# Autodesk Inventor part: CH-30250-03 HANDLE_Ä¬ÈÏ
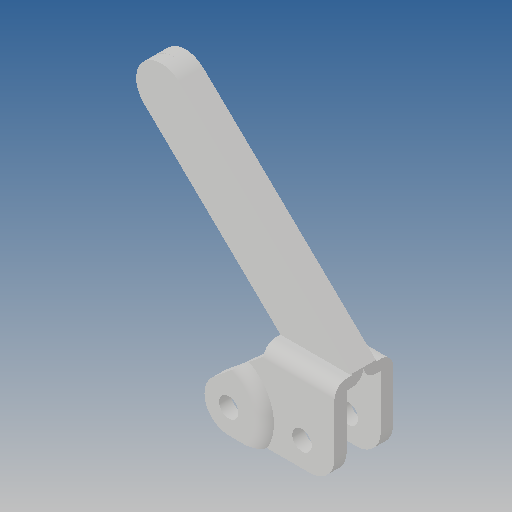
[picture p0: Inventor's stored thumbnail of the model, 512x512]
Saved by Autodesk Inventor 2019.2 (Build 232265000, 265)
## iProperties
Created: 2010-06
Part Number: CH-30250-03 HANDLE_Ä¬ÈÏ
Material: Ogólny
Document SubType Name: Modeling
Designer: CADENGINEERING4
Density: 1 g/cm^3
Appearance: Domyślna
Author: CADENGINEERING4
Revision Number: ÈÎºÎ
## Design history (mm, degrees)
feature "NONE"
feature "NONE:1"
node "Bryła1"
node "Bryła2"
